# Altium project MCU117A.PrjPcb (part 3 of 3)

## Sheet MCU117A_Hardware.SchDoc
size 431 x 279 mm; Date: Not shown in title block; ApprovedBy: Not shown in title block; CheckedBy: Not shown in title block; Author: Not shown in title block; CompanyName: Not shown in title block; Engineer: Not shown in title block; Organization: Not shown in title block; Address1: Not shown in title block; Address2: Not shown in title block; Address3: Not shown in title block; Address4: Not shown in title block; DocumentNumber: 9; Revision: Use project parameter SCH_Rev; SheetNumber: 9; SheetTotal: 9; PageSetup: Record=PageOptions¦CenterHorizontal=True¦CenterVertical=True¦PrintScale=1.00¦XCorrection=1.00¦YCorrection=1.00¦PrintKind=0¦BorderSize=5000000¦LeftOffset=0¦BottomOffset=0¦Orientation=2¦PaperLength=1000¦PaperWidth=1000¦Scale=100¦PaperSource=15¦PrintQuality=600¦MediaType=1¦DitherType=10¦PaperKind=Letter¦PrintScaleMode=1
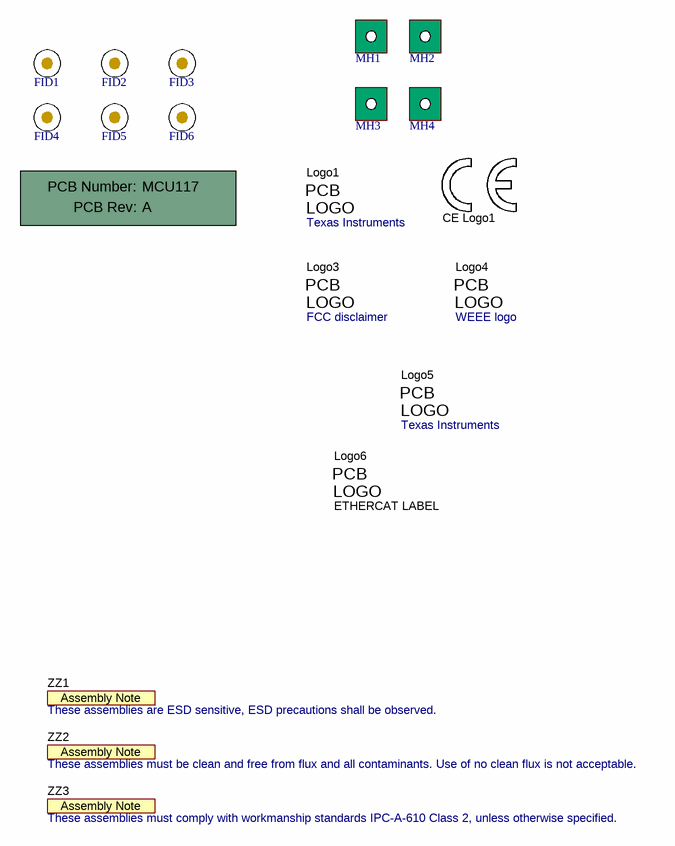
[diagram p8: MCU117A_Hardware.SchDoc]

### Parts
!PCB1  Printed Circuit Board  (value not drawn)  (mechanical)
CE_Logo1  CE Mark  [CE_Mark_5mm]  (value not drawn)  (no BOM)
FID1  Fiducial  [Fiducial10-20]  (value not drawn)
FID2  Fiducial  [Fiducial10-20]  (value not drawn)
FID3  Fiducial  [Fiducial10-20]  (value not drawn)
FID4  Fiducial  [Fiducial10-20]  (value not drawn)
FID5  Fiducial  [Fiducial10-20]  (value not drawn)
FID6  Fiducial  [Fiducial10-20]  (value not drawn)
Logo1  Texas Instruments  [TI_Stacked_Overlay_Medium]  (no BOM)
Logo3  FCC disclaimer  [FCC_disclaimer]  (no BOM)
Logo4  WEEE logo  [WEEE_Minimum]  (no BOM)
Logo5  Texas Instruments  [TI_Symbol_Overlay_Small]  (no BOM)
Logo6  ETHERCAT LABEL  [EtherCAT_label]  (no BOM)
MH1  MTG_NoPads  [NPTH125mil]  (value not drawn)  (no BOM)
MH2  MTG_NoPads  [NPTH125mil]  (value not drawn)  (no BOM)
MH3  MTG_NoPads  [NPTH125mil]  (value not drawn)  (no BOM)
MH4  MTG_NoPads  [NPTH125mil]  (value not drawn)  (no BOM)
ZZ1  These assemblies are ESD sensitive, ESD precautions shall be observed.  [AssemblyNote]  (no BOM)
ZZ2  These assemblies must be clean and free from flux and all contaminants. Use of no clean flux is not acceptable.  [AssemblyNote]  (no BOM)
ZZ3  These assemblies must comply with workmanship standards IPC-A-610 Class 2, unless otherwise specified.  [AssemblyNote]  (no BOM)

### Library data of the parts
!PCB1 = CMP-0003618-2: Manufacturer: Any; PartNumber: MCU117
CE_Logo1 = CMP-0074844-1: SymbolCreator: a0412235
FID1-FID6 = CMP-0077181-1: Fiducial mark.  There is nothing to buy or mount.
Logo1 Logo5 = CMP-0074838-1: Texas Instrument Corporate Signature; SymbolCreator: a0412235; Lib Reference: TI_Logo
Logo3 = CMP-0074847-1: FCC_disclaimer
Logo4 = CMP-0074769-1
Logo6 = CMP-0084011-3: EtherCAT logo
MH1-MH4 = CMP-0078424-2: PCB Mounting Hole, No Pad; Manufacturer: Any; Key: Mounting Hole (non-standard) No Pad
ZZ1 = CMP-0077236-1
ZZ2 = CMP-0077237-1
ZZ3 = CMP-0077238-1

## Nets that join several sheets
+1V2_MCU: MCU117A_F28P65X_Device (C59.1 L1.1), MCU117A_USB_and_Power (C118.1 R70.1)
+3V3_MCU: MCU117A_Connectors (5 pins), MCU117A_AltRouting_Misc (29 pins), MCU117A_F28P65X_Device (7 pins), MCU117A_ADC (C51.1 U3.1 U3.2), MCU117A_EtherCAT (22 pins), MCU117A_USB_and_Power (19 pins), MCU117A_XDS110_MCU (R74.2 R76.2)
+3V3_XDS110: MCU117A_USB_and_Power (C126.1 R96.1 U25.5), MCU117A_XDS110_MCU (37 pins)
+5V0_MCU: MCU117A_Connectors (10 pins), MCU117A_AltRouting_Misc (C22.2 C23.1 U13.23 U13.24), MCU117A_USB_and_Power (14 pins)
+5V0_USB: MCU117A_USB_and_Power (12 pins), MCU117A_XDS110_MCU (R164.1)
GND: MCU117A_Connectors (23 pins), MCU117A_AltRouting_Misc (39 pins), MCU117A_F28P65X_Device (37 pins), MCU117A_ADC (36 pins), MCU117A_EtherCAT (71 pins), MCU117A_USB_and_Power (39 pins), MCU117A_XDS110_MCU (13 pins)
USB_GND: MCU117A_USB_and_Power (22 pins), MCU117A_XDS110_MCU (36 pins)
VDD: MCU117A_F28P65X_Device (10 pins), MCU117A_USB_and_Power (5 pins)
VDDA: MCU117A_F28P65X_Device (5 pins), MCU117A_USB_and_Power (TP3.1)
VDDIO: MCU117A_F28P65X_Device (18 pins), MCU117A_USB_and_Power (TP2.1)
ADCINA0/DACA_OUT: MCU117A_Connectors (J1/J3.30), MCU117A_ADC (R18.1)
ADCINA4: MCU117A_Connectors (J1/J3.24), MCU117A_ADC (R38.1)
ADCINA5: MCU117A_Connectors (J5/J7.42), MCU117A_ADC (R39.1)
ADCINA7: MCU117A_Connectors (J1/J3.27), MCU117A_ADC (R40.1)
ADCINA8: MCU117A_Connectors (J5/J7.64), MCU117A_ADC (R41.1)
ADCINA10: MCU117A_Connectors (J5/J7.67), MCU117A_ADC (R42.1)
ADCINA14/B14/C14: MCU117A_Connectors (J1/J3.23), MCU117A_ADC (R43.1)
ADCINA15/B15/C15: MCU117A_Connectors (J5/J7.63), MCU117A_ADC (R45.1)
ADCINB0/VDAC: MCU117A_Connectors (J1/J3.2), MCU117A_ADC (R46.1)
ADCINB1/DACC_OUT: MCU117A_Connectors (J5/J7.70), MCU117A_ADC (R48.1)
ADCINB3: MCU117A_Connectors (J5/J7.65), MCU117A_ADC (R49.1)
ADCINB4: MCU117A_Connectors (J1/J3.25), MCU117A_ADC (R50.1)
ADCINB6: MCU117A_Connectors (J5/J7.68), MCU117A_ADC (R51.1)
ADCINB7: MCU117A_Connectors (J1/J3.28), MCU117A_ADC (R52.1)
ADCINB8B9_N: MCU117A_Connectors (J10.3), MCU117A_ADC (R55.1)
ADCINB8B9_P: MCU117A_Connectors (J10.1), MCU117A_ADC (R54.1)
ADCINC0: MCU117A_Connectors (J1/J3.6), MCU117A_ADC (R56.1)
ADCINC1: MCU117A_Connectors (J5/J7.46), MCU117A_ADC (R57.1)
ADCINC4: MCU117A_Connectors (J1/J3.26), MCU117A_ADC (R60.1)
ADCINC5: MCU117A_Connectors (J5/J7.66), MCU117A_ADC (R61.1)
ADCINC6: MCU117A_Connectors (J5/J7.69), MCU117A_ADC (R62.1)
ADCINC7: MCU117A_Connectors (J1/J3.29), MCU117A_ADC (R63.1)
ADCINC8C9_N: MCU117A_Connectors (J10.4), MCU117A_ADC (R65.1)
ADCINC8C9_P: MCU117A_Connectors (J10.2), MCU117A_ADC (R64.1)
EQEP1A: MCU117A_Connectors (C6.1 J12.1 R5.1), MCU117A_AltRouting_Misc (U13.21)
EQEP1B: MCU117A_Connectors (C7.1 J12.2 R6.1), MCU117A_AltRouting_Misc (U13.20)
EQEP1I: MCU117A_Connectors (C8.1 J12.3 R7.1), MCU117A_AltRouting_Misc (U13.19)
EQEP2A: MCU117A_Connectors (C9.1 J13.1 R8.1), MCU117A_AltRouting_Misc (U13.18)
EQEP2B: MCU117A_Connectors (C10.1 J13.2 R9.1), MCU117A_AltRouting_Misc (U13.17)
EQEP2I: MCU117A_Connectors (C11.1 J13.3 R10.1), MCU117A_AltRouting_Misc (U13.16)
GPIO0: MCU117A_Connectors (J8/J6.78), MCU117A_F28P65X_Device (U1.E7)
GPIO1: MCU117A_Connectors (J8/J6.77), MCU117A_F28P65X_Device (U1.A6)
GPIO2: MCU117A_Connectors (R3.2), MCU117A_F28P65X_Device (U1.B6)
GPIO3: MCU117A_Connectors (R4.2), MCU117A_F28P65X_Device (U1.C6)
GPIO4: MCU117A_AltRouting_Misc (S4.2), MCU117A_F28P65X_Device (U1.D6)
GPIO4_BP: MCU117A_Connectors (J4/J2.32), MCU117A_AltRouting_Misc (S4.3)
GPIO4_CANTX: MCU117A_Connectors (TP7.1 U15.1), MCU117A_AltRouting_Misc (S4.1)
GPIO5: MCU117A_AltRouting_Misc (S4.5), MCU117A_F28P65X_Device (U1.E6)
GPIO5_BP: MCU117A_Connectors (J4/J2.31), MCU117A_AltRouting_Misc (S4.6)
GPIO5_CANRX: MCU117A_Connectors (TP8.1 U15.4), MCU117A_AltRouting_Misc (S4.4)
GPIO6: MCU117A_Connectors (J4/J2.38), MCU117A_F28P65X_Device (U1.A5)
GPIO7: MCU117A_Connectors (J4/J2.37), MCU117A_F28P65X_Device (U1.B5)
GPIO8: MCU117A_Connectors (R1.2), MCU117A_F28P65X_Device (U1.E3)
GPIO9: MCU117A_Connectors (R2.2), MCU117A_F28P65X_Device (U1.F3)
GPIO10: MCU117A_Connectors (J4/J2.36), MCU117A_F28P65X_Device (U1.B3)
GPIO11: MCU117A_Connectors (J4/J2.35), MCU117A_F28P65X_Device (U1.B2)
GPIO12: MCU117A_Connectors (J4/J2.13), MCU117A_AltRouting_Misc (R17.1), MCU117A_F28P65X_Device (U1.B1)
GPIO13: MCU117A_Connectors (J8/J6.53), MCU117A_AltRouting_Misc (R19.1), MCU117A_F28P65X_Device (U1.C1)
GPIO14: MCU117A_Connectors (J4/J2.34), MCU117A_F28P65X_Device (U1.C2)
GPIO15: MCU117A_Connectors (J4/J2.33), MCU117A_F28P65X_Device (U1.C3)
GPIO16: MCU117A_Connectors (J4/J2.15), MCU117A_F28P65X_Device (U1.C4)
GPIO17: MCU117A_Connectors (J4/J2.14), MCU117A_F28P65X_Device (U1.D4)
GPIO18: MCU117A_Connectors (J1/J3.7), MCU117A_F28P65X_Device (U1.D3)
GPIO19: MCU117A_F28P65X_Device (U1.D1), MCU117A_EtherCAT (R92.2)
GPIO20: MCU117A_AltRouting_Misc (U14.14), MCU117A_F28P65X_Device (U1.E1)
GPIO21: MCU117A_AltRouting_Misc (U14.15), MCU117A_F28P65X_Device (U1.E2)
GPIO21_BP: MCU117A_Connectors (J4/J2.17), MCU117A_AltRouting_Misc (U14.1)
GPIO22: MCU117A_F28P65X_Device (U1.D2), MCU117A_EtherCAT (R203.2)
GPIO23: MCU117A_AltRouting_Misc (U14.4), MCU117A_F28P65X_Device (U1.F2)
GPIO23_BP: MCU117A_Connectors (J4/J2.12), MCU117A_AltRouting_Misc (U14.3)
GPIO24: MCU117A_AltRouting_Misc (U11.14), MCU117A_F28P65X_Device (U1.D7)
GPIO24_BP: MCU117A_Connectors (J8/J6.58), MCU117A_AltRouting_Misc (U11.13)
GPIO25: MCU117A_Connectors (J8/J6.51), MCU117A_F28P65X_Device (U1.B8)
GPIO26: MCU117A_F28P65X_Device (U1.L10), MCU117A_EtherCAT (R88.1 R119.1)
GPIO27: MCU117A_F28P65X_Device (U1.D11), MCU117A_EtherCAT (R107.1 U17.11 U20.11)
GPIO28: MCU117A_F28P65X_Device (U1.K8), MCU117A_EtherCAT (R113.2 R116.1)
GPIO29: MCU117A_F28P65X_Device (U1.L8), MCU117A_EtherCAT (R111.1 R117.1)
GPIO30: MCU117A_F28P65X_Device (U1.L9), MCU117A_EtherCAT (R106.1 U12.6)
GPIO32: MCU117A_Connectors (J8/J6.74), MCU117A_F28P65X_Device (U1.F12)
GPIO33: MCU117A_F28P65X_Device (U1.L7), MCU117A_EtherCAT (R139.1 U18.1)
GPIO34: MCU117A_Connectors (J5/J7.50), MCU117A_F28P65X_Device (U1.K7)
GPIO35: MCU117A_Connectors (J5/J7.49), MCU117A_F28P65X_Device (U1.N8)
GPIO36: MCU117A_Connectors (J8/J6.71), MCU117A_F28P65X_Device (U1.N11)
GPIO37: MCU117A_Connectors (J8/J6.72), MCU117A_F28P65X_Device (U1.M11)
GPIO38: MCU117A_AltRouting_Misc (U8.10), MCU117A_F28P65X_Device (U1.L11)
GPIO38_BP: MCU117A_Connectors (J5/J7.44 J5/J7.45), MCU117A_AltRouting_Misc (U8.9)
GPIO40: MCU117A_F28P65X_Device (U1.N12), MCU117A_EtherCAT (R105.1 U12.5)
GPIO41: MCU117A_Connectors (J8/J6.73), MCU117A_F28P65X_Device (U1.M12)
GPIO42: MCU117A_AltRouting_Misc (U6.6), MCU117A_F28P65X_Device (U1.C12)
GPIO42_BP: MCU117A_Connectors (J1/J3.4 J1/J3.5), MCU117A_AltRouting_Misc (U6.4)
GPIO43: MCU117A_AltRouting_Misc (U6.10), MCU117A_F28P65X_Device (U1.C11)
GPIO43_BP: MCU117A_Connectors (J1/J3.3), MCU117A_AltRouting_Misc (U6.2)
GPIO44: MCU117A_F28P65X_Device (U1.F10), MCU117A_EtherCAT (R146.2 R155.1)
GPIO45: MCU117A_F28P65X_Device (U1.F11), MCU117A_EtherCAT (R91.2)
GPIO48_PHYCLK: MCU117A_AltRouting_Misc (R25.1 R27.1), MCU117A_F28P65X_Device (U1.M13)
GPIO49_FSITXD0: MCU117A_Connectors (J11.6), MCU117A_F28P65X_Device (U1.L13)
GPIO50_FSITXD1: MCU117A_Connectors (J11.8), MCU117A_F28P65X_Device (U1.K9)
GPIO51_FSITXCLK: MCU117A_Connectors (J11.2), MCU117A_F28P65X_Device (U1.K10)
GPIO52_FSIRXD0: MCU117A_Connectors (J11.5), MCU117A_F28P65X_Device (U1.K11)
GPIO53_FSIRXD1: MCU117A_Connectors (J11.7), MCU117A_F28P65X_Device (U1.K12)
GPIO54_FSIRXCLK: MCU117A_Connectors (J11.1), MCU117A_F28P65X_Device (U1.K13)
GPIO55: MCU117A_AltRouting_Misc (U8.6), MCU117A_F28P65X_Device (U1.J13)
GPIO55_BP: MCU117A_Connectors (J5/J7.43), MCU117A_AltRouting_Misc (U8.7)
GPIO56: MCU117A_F28P65X_Device (U1.J12), MCU117A_EtherCAT (R58.2)
GPIO57: MCU117A_Connectors (J4/J2.19), MCU117A_F28P65X_Device (U1.J11)
GPIO58: MCU117A_F28P65X_Device (U1.J10), MCU117A_EtherCAT (RJ1.12)
GPIO59: MCU117A_F28P65X_Device (U1.H13), MCU117A_EtherCAT (RJ2.12)
GPIO61: MCU117A_F28P65X_Device (U1.H11), MCU117A_EtherCAT (R140.1 U18.3)
GPIO62: MCU117A_F28P65X_Device (U1.H10), MCU117A_EtherCAT (U17.12 U20.12)
GPIO63: MCU117A_F28P65X_Device (U1.G13), MCU117A_EtherCAT (R158.1 R162.2)
GPIO64: MCU117A_F28P65X_Device (U1.G12), MCU117A_EtherCAT (R147.2 R150.1)
GPIO65: MCU117A_F28P65X_Device (U1.G11), MCU117A_EtherCAT (R145.1 R152.1)
GPIO66: MCU117A_F28P65X_Device (U1.G10), MCU117A_EtherCAT (R133.1 R153.1)
GPIO68: MCU117A_F28P65X_Device (U1.B13), MCU117A_EtherCAT (R163.1 RJ2.1 U20.31)
GPIO69: MCU117A_F28P65X_Device (U1.B12), MCU117A_EtherCAT (R148.1)
GPIO70: MCU117A_F28P65X_Device (U1.A12), MCU117A_EtherCAT (R149.1 R161.2)
GPIO71: MCU117A_F28P65X_Device (U1.B11), MCU117A_EtherCAT (R130.1 R154.1)
GPIO72: MCU117A_Connectors (J1/J3.8), MCU117A_AltRouting_Misc (R31.1), MCU117A_F28P65X_Device (U1.A11)
GPIO73: MCU117A_F28P65X_Device (U1.C10), MCU117A_EtherCAT (R110.2)
GPIO74: MCU117A_F28P65X_Device (U1.B10), MCU117A_EtherCAT (R144.2)
GPIO75: MCU117A_Connectors (J8/J6.75), MCU117A_F28P65X_Device (U1.A10)
GPIO76: MCU117A_F28P65X_Device (U1.E9), MCU117A_EtherCAT (R32.2 R141.2 U17.32 U20.32)
GPIO77: MCU117A_F28P65X_Device (U1.D9), MCU117A_EtherCAT (R114.1)
GPIO78: MCU117A_F28P65X_Device (U1.C9), MCU117A_EtherCAT (R115.1 R127.2)
GPIO79: MCU117A_AltRouting_Misc (U11.15), MCU117A_F28P65X_Device (U1.B9)
GPIO79_BP: MCU117A_Connectors (J8/J6.57), MCU117A_AltRouting_Misc (U11.1)
GPIO80: MCU117A_F28P65X_Device (U1.E8), MCU117A_EtherCAT (R126.1 R128.2)
GPIO82: MCU117A_Connectors (J5/J7.48), MCU117A_F28P65X_Device (U1.D8)
GPIO83: MCU117A_F28P65X_Device (U1.C8), MCU117A_EtherCAT (R89.1 R118.1)
GPIO84: MCU117A_Connectors (J4/J2.18), MCU117A_AltRouting_Misc (R33.2), MCU117A_F28P65X_Device (U1.A8)
GPIO85: MCU117A_F28P65X_Device (U1.A7), MCU117A_EtherCAT (R112.2 R120.1)
GPIO86: MCU117A_F28P65X_Device (U1.B7), MCU117A_EtherCAT (R129.2 RJ1.1 U17.31)
GPIO87: MCU117A_F28P65X_Device (U1.C7), MCU117A_EtherCAT (R87.2)
GPIO88: MCU117A_F28P65X_Device (U1.C5), MCU117A_EtherCAT (R86.2)
GPIO89: MCU117A_F28P65X_Device (U1.D5), MCU117A_EtherCAT (R84.2)
GPIO90: MCU117A_F28P65X_Device (U1.E5), MCU117A_EtherCAT (R83.2)
GPIO91: MCU117A_Connectors (J8/J6.55), MCU117A_F28P65X_Device (U1.B4)
GPIO92: MCU117A_Connectors (J8/J6.54), MCU117A_F28P65X_Device (U1.A4)
GPIO93: MCU117A_Connectors (J5/J7.47), MCU117A_F28P65X_Device (U1.A3)
GPIO94: MCU117A_Connectors (J8/J6.59), MCU117A_F28P65X_Device (U1.A2)
GPIO99: MCU117A_Connectors (J8/J6.76), MCU117A_F28P65X_Device (U1.E4)
GPIO103: MCU117A_AltRouting_Misc (U11.4), MCU117A_F28P65X_Device (U1.D10)
GPIO103_BP: MCU117A_Connectors (J8/J6.52), MCU117A_AltRouting_Misc (U11.3)
GPIO104: MCU117A_Connectors (J1/J3.10), MCU117A_F28P65X_Device (U1.A9)
GPIO105: MCU117A_Connectors (J1/J3.9), MCU117A_F28P65X_Device (U1.H12)
GPIO133: MCU117A_Connectors (J4/J2.11), MCU117A_F28P65X_Device (U1.F13)
MCU_RXD: MCU117A_AltRouting_Misc (U9.6), MCU117A_XDS110_MCU (R165.1)
MCU_TCK: MCU117A_F28P65X_Device (U1.M10), MCU117A_XDS110_MCU (R98.1)
MCU_TDI: MCU117A_F28P65X_Device (U1.N9), MCU117A_XDS110_MCU (R99.1)
MCU_TDO: MCU117A_F28P65X_Device (U1.M9), MCU117A_XDS110_MCU (R100.1)
MCU_TMS: MCU117A_F28P65X_Device (R44.1 U1.N10), MCU117A_XDS110_MCU (R97.1)
MCU_TXD: MCU117A_AltRouting_Misc (U9.10), MCU117A_XDS110_MCU (R171.1)
PHY0_CLK: MCU117A_AltRouting_Misc (R27.2 R29.1), MCU117A_EtherCAT (U17.9)
PHY1_CLK: MCU117A_AltRouting_Misc (R25.2 R28.1), MCU117A_EtherCAT (U20.9)
USB_D_N: MCU117A_USB_and_Power (U16.1 U16.10 USB1.A7 USB1.B7), MCU117A_XDS110_MCU (U2.93)
USB_D_P: MCU117A_USB_and_Power (U16.2 U16.9 USB1.A6 USB1.B6), MCU117A_XDS110_MCU (U2.94)
X1: MCU117A_AltRouting_Misc (R20.2), MCU117A_F28P65X_Device (U1.D13)
XRSn: MCU117A_Connectors (J4/J2.16 J8/J6.56), MCU117A_F28P65X_Device (C28.1 R59.1 S1.4 U1.D12), MCU117A_USB_and_Power (R95.1)

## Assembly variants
001: not fitted C1 C2 C3 C4 C24 C25 C26 C27 C29 C30 C31 C32 C33 C34 C35 C36 C37 C38 C39 C40 C41 C42 C43 C44 C45 C46 C47 C48 C49 C50 C80 C91 C92 C93 C94 C107 C108 C109 C110 FID1 FID2 FID3 FID4 FID5 FID6 R23 R25 R26 R27 R30 R34 R53 R68 R175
